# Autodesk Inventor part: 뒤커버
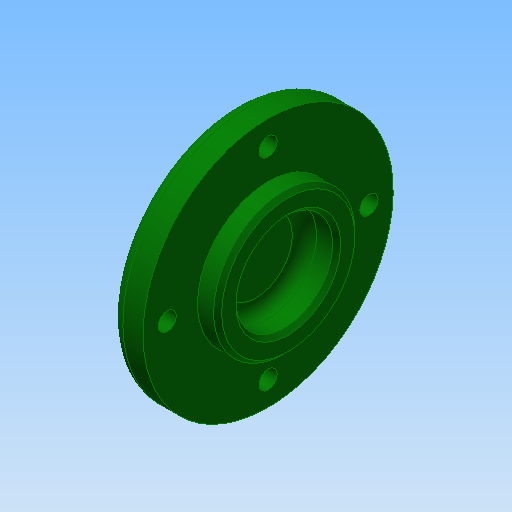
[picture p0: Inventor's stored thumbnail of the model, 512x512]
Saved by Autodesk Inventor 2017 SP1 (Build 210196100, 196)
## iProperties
Created: 2015-12
Part Number: 뒤커버
Document SubType Name: Modeling
Designer: mdu
Density: 2.71 g/cm^3
Material: 알루미늄 6061
Mass: 72.2029 g
Surface Area: 89.061 cm^2
Volume: 26.6431 cm^3
Appearance: 진녹색
Author: mdu
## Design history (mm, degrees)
sketch "스케치1"
  geometry: L1 (-8, 0)-(8, 0); L2 (-8, 0)-(-8, 15.5); L3 (-8, 15.5)-(-5, 18.5); L4 (-5, 18.5)-(-5, 31); L5 (-5, 31)-(3, 31); L6 (3, 31)-(3, 17.5); L7 (3, 17.5)-(8, 17.5); L8 (8, 17.5)-(8, 0); 2 further points
  constraints: 16 end point, 4 parallel, 2 perpendicular, 1 coincident, 1 horizontal, 1 midpoint
  dimensions: "d0" = 16 distance of L1.start L1.end; "d1" = 62 diameter of L5 L1; "d2" = 35 diameter of L7 L1; "d3" = 37 diameter of L3.end L1; "d5" = 8 distance of L4.end L5.end; "d34" = 135 deg angle of L4 L3; "d36" = 5 distance of L6.end L7.end
revolve "회전1" sketch "스케치1" stored, may be unused: angle "d6" = 90 deg
sketch "스케치2" dims "d32" = 50
  geometry: 3 further points
  constraints: 2 vertical alignment, 1 coincident, 2 other
hole "구멍1" sketch "스케치2" at (0, 25) diameter "d8" = 4.5; stored, may be unused: countersink angle "d12" = 90 deg, drill point angle "d14" = 118 deg; dims "d9" = 6, "d10" = 8, "d11" = 4.4, "d13" = 8
hole "구멍2" diameter "d20" = 24; stored, may be unused: countersink angle "d24" = 90 deg, drill point angle "d26" = 0 deg; dims "d18" = 10, "d19" = 10, "d21" = 6, "d22" = 8, "d23" = 4.4, "d25" = 8
fillet "모깎기1" dims "d27" = 3
fillet "모깎기2" dims "d28" = 3
chamfer "모따기1" distance "d29" = 1; stored, may be unused: second distance "d30" = 2, angle "d31" = 45 deg
node "솔리드1"
pattern_circular "원형 패턴1" dims angle "d16" = 360 deg
